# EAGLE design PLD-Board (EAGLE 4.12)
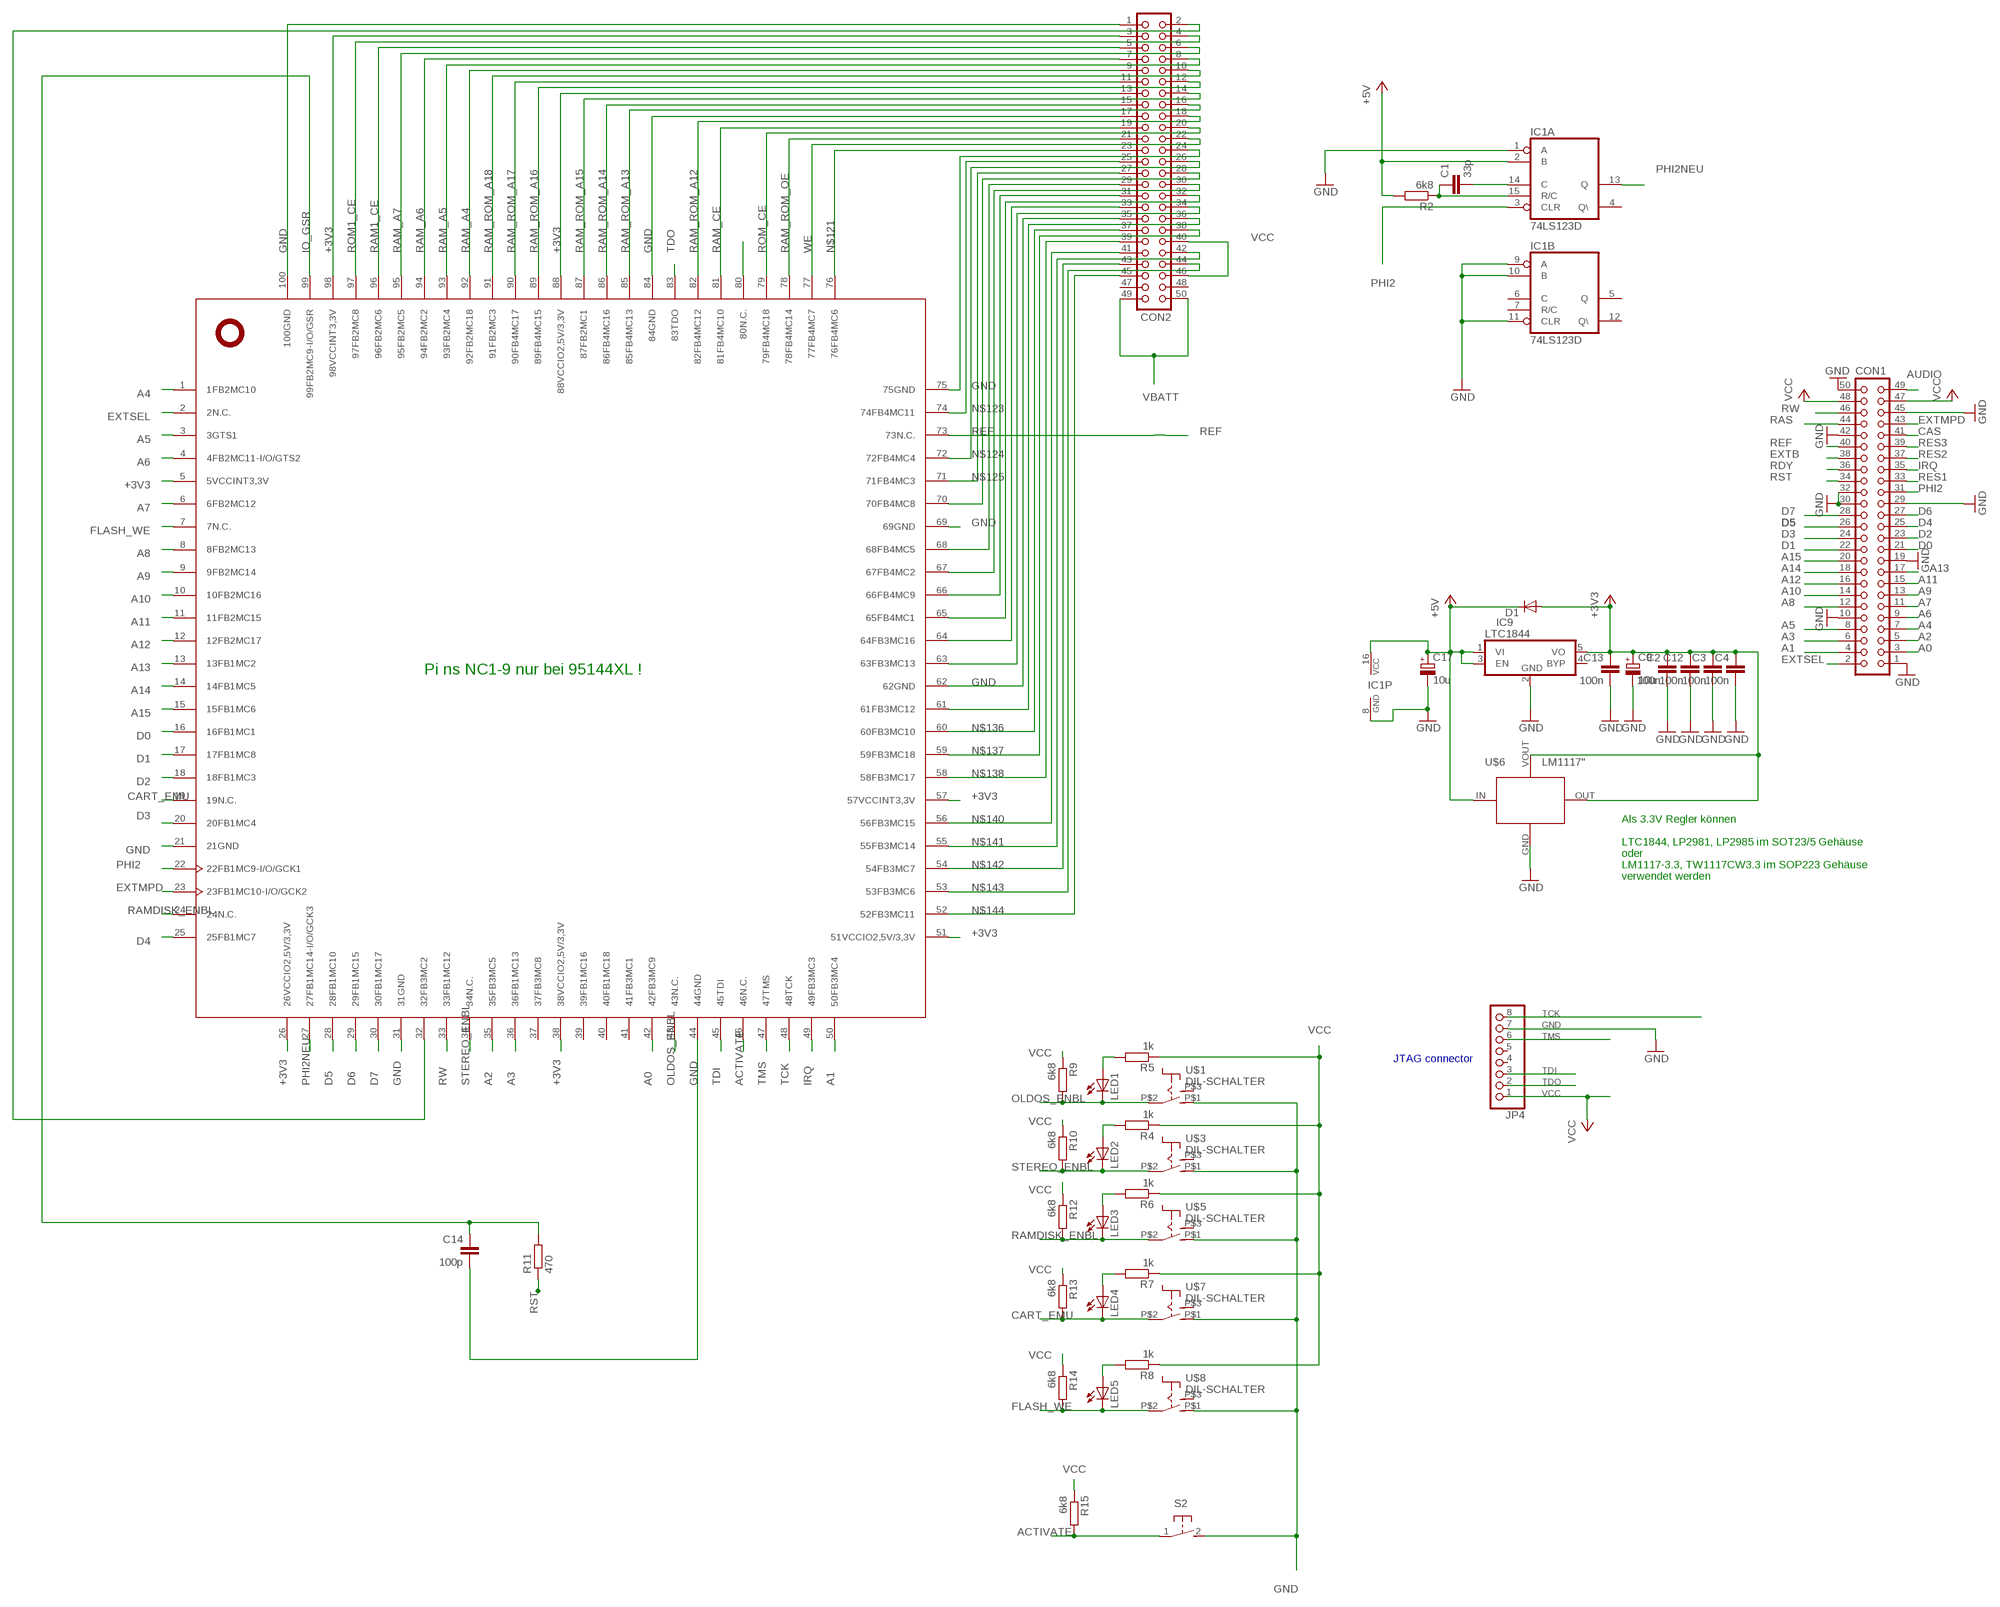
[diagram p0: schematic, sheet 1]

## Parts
C1  33p  C-EUC0805  [C0805]
C2  100n  C-EUC1206  [C1206]
C3  100n  C-EUC1206  [C1206]
C4  100n  C-EUC1206  [C1206]
C9  10u  CPOL-EUB/3528-21W  [B/3528-21W]
C12  100n  C-EUC1206  [C1206]
C13  100n  C-EUC1206  [C1206]
C14  100p  C-EUC0805  [C0805]
C17  10u  CPOL-EUB/3528-21W  [B/3528-21W]
CON1  CON50  [CON50]
CON2  CON50  [CON50]
D1  DIODE-DO214BA  [DO-214BA]
IC1  74LS123D  [SO16]
IC9  LTC1844  [SOT23/5]
JP4  PINHD-1X8  [1X08]
LED1  LEDCHIPLED_1206  [CHIPLED_1206]
LED2  LEDCHIPLED_1206  [CHIPLED_1206]
LED3  LEDCHIPLED_1206  [CHIPLED_1206]
LED4  LEDCHIPLED_1206  [CHIPLED_1206]
LED5  LEDCHIPLED_1206  [CHIPLED_1206]
R2  6k8  R-EU_M0805  [M0805]
R4  1k  R-EU_M0805  [M0805]
R5  1k  R-EU_M0805  [M0805]
R6  1k  R-EU_M0805  [M0805]
R7  1k  R-EU_M0805  [M0805]
R8  1k  R-EU_M0805  [M0805]
R9  6k8  R-EU_M0805  [M0805]
R10  6k8  R-EU_M0805  [M0805]
R11  470  R-EU_M0805  [M0805]
R12  6k8  R-EU_M0805  [M0805]
R13  6k8  R-EU_M0805  [M0805]
R14  6k8  R-EU_M0805  [M0805]
R15  6k8  R-EU_M0805  [M0805]
S2  31-XX  [B3F-31XX]
U$1  DIL-SCHALTER  [DIL-SCHALTER]
U$2  XC9572XLTQ100  [TQ100]
U$3  DIL-SCHALTER  [DIL-SCHALTER]
U$5  DIL-SCHALTER  [DIL-SCHALTER]
U$6  LM1117"  [SOT-223]
U$7  DIL-SCHALTER  [DIL-SCHALTER]
U$8  DIL-SCHALTER  [DIL-SCHALTER]

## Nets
+3V3: C2.1 C3.1 C4.1 C9.+ C12.1 C13.1 CON2.3 CON2.13 D1.A IC9.5(VO) U$2.5(5VCCINT3,3V) U$2.26(26VCCIO2,5V/3,3V) U$2.38(38VCCIO2,5V/3,3V) U$2.51(51VCCIO2,5V/3,3V) U$2.57(57VCCINT3,3V) U$2.88(88VCCIO2,5V/3,3V) U$2.98(98VCCINT3,3V) U$6.OUT U$6.VOUT(CASE)
A0: CON1.3 U$2.42(42FB3MC9)
A1: CON1.4 U$2.50(50FB3MC4)
A2: CON1.5 U$2.35(35FB3MC5)
A3: CON1.6 U$2.36(36FB1MC13)
A4: CON1.7 U$2.1(1FB2MC10)
A5: CON1.8 U$2.3(3GTS1)
A6: CON1.9 U$2.4(4FB2MC11-I/O/GTS2)
A7: CON1.11 U$2.6(6FB2MC12)
A8: CON1.12 U$2.8(8FB2MC13)
A9: CON1.13 U$2.9(9FB2MC14)
A10: CON1.14 U$2.10(10FB2MC16)
A11: CON1.15 U$2.11(11FB2MC15)
A12: CON1.16 U$2.12(12FB2MC17)
A13: CON1.17 U$2.13(13FB1MC2)
A14: CON1.18 U$2.14(14FB1MC5)
A15: CON1.20 U$2.15(15FB1MC6)
ACTIVATE: R15.2 S2.1(P) U$2.46(46N.C.)
AUDIO: CON1.49
CART_EMU: LED4.C R13.2 U$2.19(19N.C.) U$7.P$2(P)
CAS: CON1.41
D0: CON1.21 U$2.16(16FB1MC1)
D1: CON1.22 U$2.17(17FB1MC8)
D2: CON1.23 U$2.18(18FB1MC3)
D3: CON1.24 U$2.20(20FB1MC4)
D4: CON1.25 U$2.25(25FB1MC7)
D5: CON1.26 U$2.28(28FB1MC10)
D6: CON1.27 U$2.29(29FB1MC15)
D7: CON1.28 U$2.30(30FB1MC17)
DEB_LED1: CON2.28 U$2.70(70FB4MC8)
DEB_LED2: CON2.29 U$2.68(68FB4MC5)
DEB_LED3: CON2.30 U$2.67(67FB4MC2)
DEB_LED4: CON2.32 U$2.65(65FB4MC1)
DEB_LED5: CON2.31 U$2.66(66FB4MC9)
DEB_LED6: CON2.34 U$2.63(63FB3MC13)
DEB_LED7: CON2.33 U$2.64(64FB3MC16)
DEB_LED8: CON2.36 U$2.61(61FB3MC12)
EXTB: CON1.38
EXTMPD: CON1.43 U$2.23(23FB1MC10-I/O/GCK2)
EXTSEL: CON1.2 U$2.2(2N.C.)
FLASH_WE: LED5.C R14.2 U$2.7(7N.C.) U$8.P$2(P)
GND: C2.2 C3.2 C4.2 C9.- C12.2 C13.2 C14.2 C17.- CON1.1 CON1.10 CON1.19 CON1.29 CON1.30 CON1.32 CON1.42 CON1.45 CON1.50 CON2.1 CON2.17 CON2.24 CON2.35 IC1.1(A:A) IC1.8(P:GND) IC1.9(B:A) IC1.10(B:B) IC1.11(B:CLR) IC9.2(GND) JP4.7 S2.2(S) U$1.P$1(S) U$2.21(21GND) U$2.31(31GND) U$2.44(44GND) U$2.62(62GND) U$2.69(69GND) U$2.75(75GND) U$2.84(84GND) U$2.100(100GND) U$3.P$1(S) U$5.P$1(S) U$6.GND U$7.P$1(S) U$8.P$1(S)
IO_GSR: CON2.2 U$2.32(32FB3MC2)
IRQ: CON1.35 U$2.49(49FB3MC3)
N$16: C14.1 R11.2 U$2.99(99FB2MC9-I/O/GSR)
N$28: LED5.A R8.2
N$29: C1.2 IC1.14(A:C)
N$30: LED1.A R5.2
N$31: LED2.A R4.2
N$32: LED3.A R6.2
N$33: LED4.A R7.2
N$34: C1.1 IC1.15(A:R/C) R2.1
N$38: U$2.80(80N.C.)
N$121: CON2.23 U$2.76(76FB4MC6)
N$123: CON2.25 U$2.74(74FB4MC11)
N$124: CON2.26 U$2.72(72FB4MC4)
N$125: CON2.27 U$2.71(71FB4MC3)
N$136: CON2.37 U$2.60(60FB3MC10)
N$137: CON2.38 U$2.59(59FB3MC18)
N$138: CON2.39 U$2.58(58FB3MC17)
N$140: CON2.41 U$2.56(56FB3MC15)
N$141: CON2.42 U$2.55(55FB3MC14)
N$142: CON2.43 U$2.54(54FB3MC7)
N$143: CON2.44 U$2.53(53FB3MC6)
N$144: CON2.45 U$2.52(52FB3MC11)
OLDOS_ENBL: LED1.C R9.2 U$1.P$2(P) U$2.43(43N.C.)
PHI2: CON1.31 IC1.3(A:CLR) U$2.22(22FB1MC9-I/O/GCK1)
PHI2NEU: IC1.13(A:Q) U$2.27(27FB1MC14-I/O/GCK3)
RAM1_CE: CON2.5 U$2.96(96FB2MC6)
RAM_A4: CON2.9 U$2.92(92FB2MC18)
RAM_A5: CON2.8 U$2.93(93FB2MC4)
RAM_A6: CON2.7 U$2.94(94FB2MC2)
RAM_A7: CON2.6 U$2.95(95FB2MC5)
RAM_CE: CON2.19 U$2.81(81FB4MC10)
RAM_ROM_A12: CON2.18 U$2.82(82FB4MC12)
RAM_ROM_A13: CON2.16 U$2.85(85FB4MC13)
RAM_ROM_A14: CON2.15 U$2.86(86FB4MC16)
RAM_ROM_A15: CON2.14 U$2.87(87FB2MC1)
RAM_ROM_A16: CON2.12 U$2.89(89FB4MC15)
RAM_ROM_A17: CON2.11 U$2.90(90FB4MC17)
RAM_ROM_A18: CON2.10 U$2.91(91FB2MC3)
RAM_ROM_OE: CON2.21 U$2.78(78FB4MC14)
RAMDISK_ENBL: LED3.C R12.2 U$2.24(24N.C.) U$5.P$2(P)
RAS: CON1.44
RDY: CON1.36
REF: CON1.40 U$2.73(73N.C.)
RES1: CON1.33
RES2: CON1.37
RES3: CON1.39
ROM1_CE: CON2.4 U$2.97(97FB2MC8)
ROM_CE: CON2.20 U$2.79(79FB4MC18)
RST: CON1.34 R11.1
RW: CON1.46 U$2.33(33FB1MC12)
STEREO_ENBL: LED2.C R10.2 U$2.34(34N.C.) U$3.P$2(P)
TCK: JP4.8 U$2.48(48TCK)
TDI: JP4.3 U$2.45(45TDI)
TDO: JP4.2 U$2.83(83TDO)
TMS: JP4.6 U$2.47(47TMS)
VBATT: CON2.49 CON2.50
VCC: C17.+ CON1.47 CON1.48 CON2.40 CON2.46 D1.C IC1.2(A:B) IC1.16(P:VCC) IC9.1(VI) IC9.3(EN) JP4.1 R2.2 R4.1 R5.1 R6.1 R7.1 R8.1 R9.1 R10.1 R12.1 R13.1 R14.1 R15.1 U$6.IN ; supply symbol labelled +5V
WE: CON2.22 U$2.77(77FB4MC7)
Unconnected: CON2.47 CON2.48 IC1.4(A:Q\) IC1.5(B:Q) IC1.6(B:C) IC1.7(B:R/C) IC1.12(B:Q\) IC9.4(BYP) JP4.4 JP4.5 U$1.P$3(S1) U$2.37(37FB3MC8) U$2.39(39FB1MC16) U$2.40(40FB1MC18) U$2.41(41FB3MC1) U$3.P$3(S1) U$5.P$3(S1) U$7.P$3(S1) U$8.P$3(S1)

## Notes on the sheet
- Pi ns NC1-9 nur bei 95144XL !
- Als 3.3V Regler können
- LTC1844, LP2981, LP2985 im SOT23/5 Gehäuse
- oder
- LM1117-3.3, TW1117CW3.3 im SOP223 Gehäuse
- verwendet werden
- JTAG connector

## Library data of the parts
C1-C4 C12-C14 = rcl:C-EU: CAPACITOR, European symbol
C9 C17 = rcl:CPOL-EU: POLARIZED CAPACITOR, European symbol
CON1 CON2 = con-harting:CON50: CONNECTOR
D1 = diode:DIODE-: DIODE
IC1 = 74xx-eu:74*123: Retriggerable monostable MULTIVIBRATOR
IC9 = Sonstiges:LTC1844
JP4 = pinhead:PINHD-1X8: PIN HEADER
LED1-LED5 = led:LED: LED
R2 R4-R15 = rcl:R-EU_: RESISTOR, European symbol
S2 = switch-omron:31-XX: OMRON SWITCH
U$1 U$3 U$5 U$7 U$8 = wf-atari:DIL-SCHALTER
U$2 = xilinx_xc9572xl-tq100:XC9572XLTQ100
U$6 = lm1117:LM1117

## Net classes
2 3.3: width 0.508 mm, drill 0.254 mm

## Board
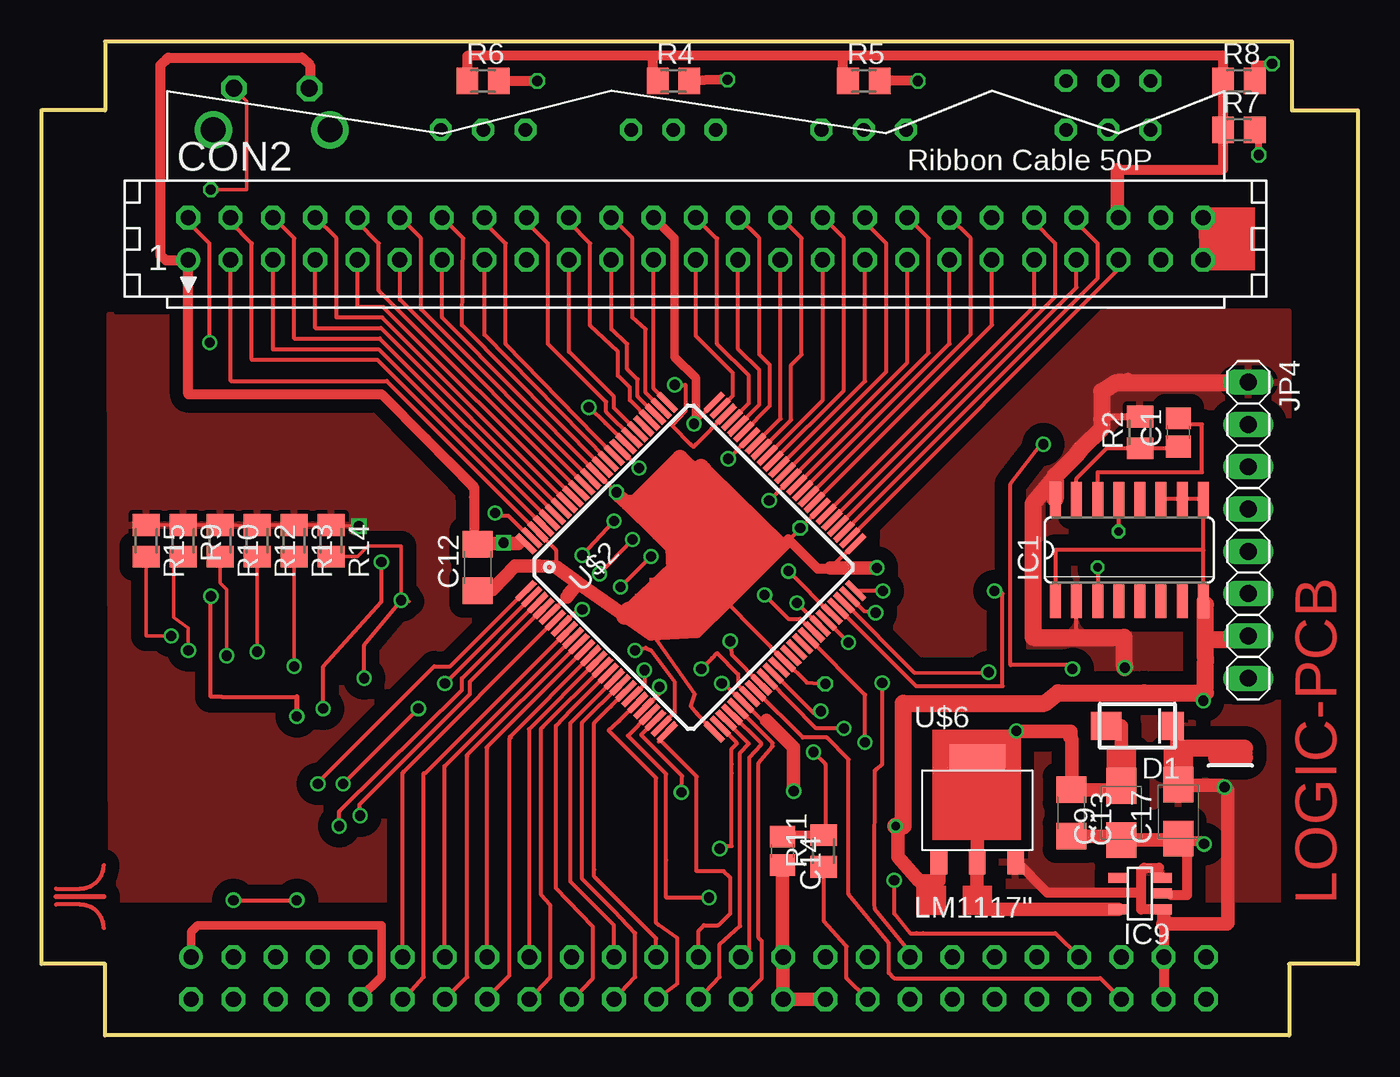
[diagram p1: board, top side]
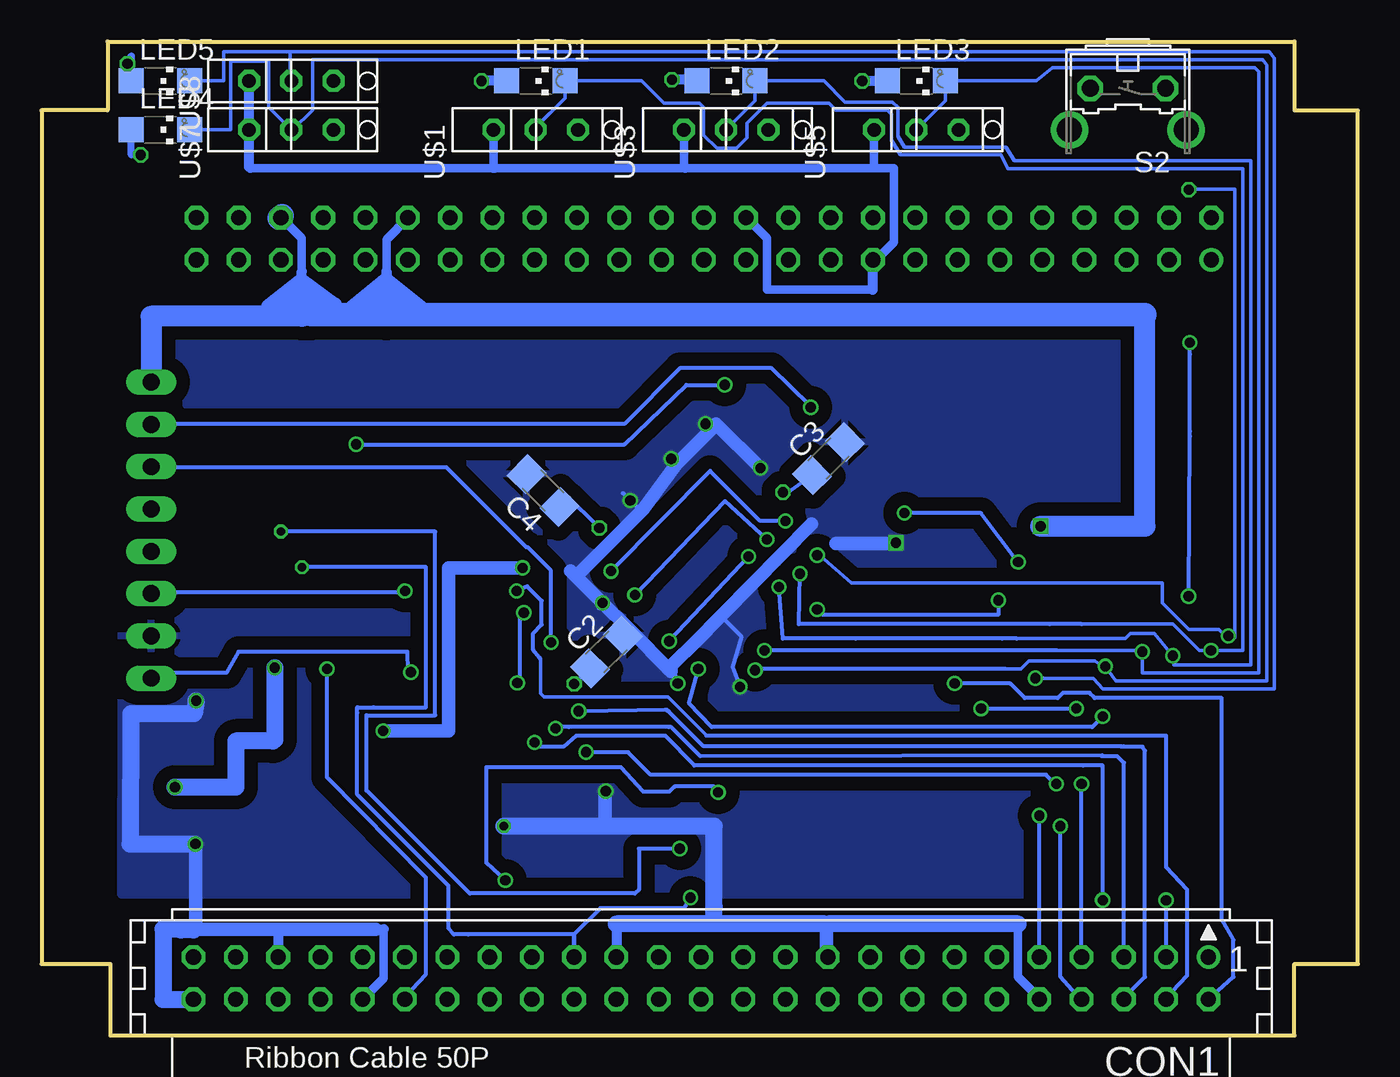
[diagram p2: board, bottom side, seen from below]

Size 79.06 x 59.69 mm. Coordinates in mm from the lower left corner, seen from the top.
Outline: 75.09,59.69 75.09,59.69
Outline: 75.09,59.69 3.81,59.69 3.81,55.56 0,55.56 0,4.29 3.81,4.29 3.81,0 74.93,0 74.93,4.29 79.06,4.29 79.06,55.56 75.09,55.56 75.09,59.69
Copper layers (1*16): Top 0.035mm / dielectric 1.5mm / Bottom 0.035mm
Design rules "ITead_rule": minimum track width 6mil, minimum drill 12mil, track to track 6mil, track to pad 6mil, pad to pad 6mil, via to via 6mil, smd to smd 0mil, copper to edge 10mil, drill to drill 10mil, minimum pad ring 10mil, minimum via ring 6mil, stop-mask expansion 2mil, vias tented up to drill 100mil, thermal gap 10mil

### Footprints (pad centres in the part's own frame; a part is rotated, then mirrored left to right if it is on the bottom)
C0805 = smd 1.3 x 1.5: 1 -0.85,0; 2 0.85,0
C1206 = smd 1.6 x 1.8: 1 -1.4,0; 2 1.4,0
B/3528-21W = smd 2.15 x 1.8: + 1.625,0; - -1.625,0
CON50 = drill 0.914 round: 1 -30.48,-1.27 | drill 0.914 octagon: 2 -30.48,1.27; 3 -27.94,-1.27; 4 -27.94,1.27; 5 -25.4,-1.27; 6 -25.4,1.27; 7 -22.86,-1.27; 8 -22.86,1.27; 9 -20.32,-1.27; 10 -20.32,1.27; 11 -17.78,-1.27; 12 -17.78,1.27; 13 -15.24,-1.27; 14 -15.24,1.27; 15 -12.7,-1.27; 16 -12.7,1.27; 17 -10.16,-1.27; 18 -10.16,1.27; 19 -7.62,-1.27; 20 -7.62,1.27; 21 -5.08,-1.27; 22 -5.08,1.27; 23 -2.54,-1.27; 24 -2.54,1.27; 25 0,-1.27; 26 0,1.27; 27 2.54,-1.27; 28 2.54,1.27; 29 5.08,-1.27; 30 5.08,1.27; 31 7.62,-1.27; 32 7.62,1.27; 33 10.16,-1.27; 34 10.16,1.27; 35 12.7,-1.27; 36 12.7,1.27; 37 15.24,-1.27; 38 15.24,1.27; 39 17.78,-1.27; 40 17.78,1.27; 41 20.32,-1.27; 42 20.32,1.27; 43 22.86,-1.27; 44 22.86,1.27; 45 25.4,-1.27; 46 25.4,1.27; 47 27.94,-1.27; 48 27.94,1.27; 49 30.48,-1.27; 50 30.48,1.27
DO-214BA = smd 1.85 x 1.68: A 1.87,0 | smd 1.32 x 1.68: C -2.12,0
SO16 = smd 0.66 x 2.032: 1 -4.445,-3.073; 2 -3.175,-3.073; 3 -1.905,-3.073; 4 -0.635,-3.073; 5 0.635,-3.073; 6 1.905,-3.073; 7 3.175,-3.073; 8 4.445,-3.073; 9 4.445,3.073; 10 3.175,3.073; 11 1.905,3.073; 12 0.635,3.073; 13 -0.635,3.073; 14 -1.905,3.073; 15 -3.175,3.073; 16 -4.445,3.073
SOT23/5 = smd 0.6 x 1.2: 1 -0.95,-1.306; 2 0,-1.306; 3 0.95,-1.306; 4 0.95,1.306; 5 -0.95,1.306
1X08 = drill 1.016 long: 1 -8.89,0; 2 -6.35,0; 3 -3.81,0; 4 -1.27,0; 5 1.27,0; 6 3.81,0; 7 6.35,0; 8 8.89,0
CHIPLED_1206 = smd 1.5 x 1.5: A 0,-1.75; C 0,1.75
M0805 = smd 1.3 x 1.6: 1 -0.95,0; 2 0.95,0
B3F-31XX = drill 1.016 octagon: 1 -2.261,-1.245; 2 2.261,-1.245 | drill 1.499 pad 2.159 round: 3 -3.505,1.245; 4 3.505,1.245
DIL-SCHALTER = drill 0.813 octagon: P$1 0,2.54; P$2 0,0; P$3 0,-2.54
TQ100 = smd 1.5 x 0.35: 1 -4.19,3.46; 2 -4.19,2.96; 3 -4.19,2.46; 4 -4.19,1.96; 5 -4.19,1.46; 6 -4.19,0.96; 7 -4.19,0.46; 8 -4.19,-0.04; 9 -4.19,-0.54; 10 -4.19,-1.04; 11 -4.19,-1.54; 12 -4.19,-2.04; 13 -4.19,-2.54; 14 -4.19,-3.04; 15 -4.19,-3.54; 16 -4.19,-4.04; 17 -4.19,-4.54; 18 -4.19,-5.04; 19 -4.19,-5.54; 20 -4.19,-6.04; 21 -4.19,-6.54; 22 -4.19,-7.04; 23 -4.19,-7.54; 24 -4.19,-8.04; 25 -4.19,-8.54; 51 11.81,-8.54; 52 11.81,-8.04; 53 11.81,-7.54; 54 11.81,-7.04; 55 11.81,-6.54; 56 11.81,-6.04; 57 11.81,-5.54; 58 11.81,-5.04; 59 11.81,-4.54; 60 11.81,-4.04; 61 11.81,-3.54; 62 11.81,-3.04; 63 11.81,-2.54; 64 11.81,-2.04; 65 11.81,-1.54; 66 11.81,-1.04; 67 11.81,-0.54; 68 11.81,-0.04; 69 11.81,0.46; 70 11.81,0.96; 71 11.81,1.46; 72 11.81,1.96; 73 11.81,2.46; 74 11.81,2.96; 75 11.81,3.46 | smd 0.35 x 1.5: 26 -2.19,-10.54; 27 -1.69,-10.54; 28 -1.19,-10.54; 29 -0.69,-10.54; 30 -0.19,-10.54; 31 0.31,-10.54; 32 0.81,-10.54; 33 1.31,-10.54; 34 1.81,-10.54; 35 2.31,-10.54; 36 2.81,-10.54; 37 3.31,-10.54; 38 3.81,-10.54; 39 4.31,-10.54; 40 4.81,-10.54; 41 5.31,-10.54; 42 5.81,-10.54; 43 6.31,-10.54; 44 6.81,-10.54; 45 7.31,-10.54; 46 7.81,-10.54; 47 8.31,-10.54; 48 8.81,-10.54; 49 9.31,-10.54; 50 9.81,-10.54; 76 9.81,5.46; 77 9.31,5.46; 78 8.81,5.46; 79 8.31,5.46; 80 7.81,5.46; 81 7.31,5.46; 82 6.81,5.46; 83 6.31,5.46; 84 5.81,5.46; 85 5.31,5.46; 86 4.81,5.46; 87 4.31,5.46; 88 3.81,5.46; 89 3.31,5.46; 90 2.81,5.46; 91 2.31,5.46; 92 1.81,5.46; 93 1.31,5.46; 94 0.81,5.46; 95 0.31,5.46; 96 -0.19,5.46; 97 -0.69,5.46; 98 -1.19,5.46; 99 -1.69,5.46; 100 -2.19,5.46
SOT-223 = smd 1 x 1.5: GND -2.3,-3; IN 2.3,-3; OUT 0,-3 | smd 3.3 x 1.5: VOUT 0,3.3

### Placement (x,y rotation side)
C1  68.27,36.22 90 top
C2  45.14,23.03 45 bottom
C3  31.8,34.64 45 bottom
C4  48.94,32.72 135 bottom
C9  64.86,13.36 90 top
C12  26.2,28.1 90 top
C13  61.84,13.36 270 top
C14  44.51,11.08 270 top
C17  68.27,13.44 90 top
CON1  39.46,3.43 180 bottom
CON2  39.29,47.84 0 top
D1  65.81,18.59 180 top
IC1  65.33,29.15 0 top
IC9  65.97,8.51 90 top
JP4  72.48,30.34 270 top
LED1  49.38,57.33 270 bottom
LED2  37.95,57.33 270 bottom
LED3  26.52,57.33 270 bottom
LED4  71.92,54.39 270 bottom
LED5  71.92,57.33 270 bottom
R2  65.97,36.22 90 top
R4  37.95,57.33 0 top
R5  49.38,57.33 0 top
R6  26.52,57.33 0 top
R7  71.92,54.39 0 top
R8  71.92,57.33 0 top
R9  8.5,29.71 270 top
R10  10.72,29.71 270 top
R11  46.97,11.07 90 top
R12  12.95,29.71 270 top
R13  15.17,29.71 270 top
R14  17.39,29.71 270 top
R15  6.28,29.71 270 top
S2  13.81,55.64 180 bottom
U$1  49.38,54.39 90 bottom
U$2  34.5,27.22 45 top
U$3  37.95,54.39 90 bottom
U$5  26.52,54.39 90 bottom
U$6  56.2,13.41 0 top
U$7  64.06,54.39 90 bottom
U$8  64.06,57.33 90 bottom

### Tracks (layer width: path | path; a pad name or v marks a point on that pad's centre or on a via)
+3V3  (via drill 0.61)
  Top 0.229: 11.36,39.31 20.73,39.31 U$2.98 30.88,29.15 30.88,28.2 | 24.06,46.56 24.06,43.12 33.19,33.91 | 30.88,28.2 | 30.88,28.2 30.88,28.12
  Top 0.254: U$2.5 30.49,25.26 | U$2.5 30.52,25.29 | 31.56,26.33 | 30.52,25.29 31.56,26.33 | 30.52,25.29 U$2.5 | 31.68,26.53 30.52,25.29 | 34.46,32.64 | 34.46,32.64 33.33,33.77 U$2.88 33.26,33.84 33.19,33.91 | 40.39,18.22 U$2.26 | 41.12,26.02 U$2.38 44.69,22.46 45.96,21.19 v47.07,21.11 | U$2.51 47.35,28.04 47.39,28.08 | 44.64,29.53 44.62,29.51 | 44.64,29.53 44.48,29.45 | U$2.57 45.73,30.63 | 44.64,29.53 44.83,29.73 44.87,29.77 45.73,30.63 | 11.36,39.31 11.36,46.59 | 24.06,46.56 CON2.13 | 36.6,24.11 38.58,24.39 | 40.39,18.22 | 40.39,18.22 39.38,19.31 38.98,19.79 | 38.98,19.79 | 38.98,19.79 39.22,20.5 36.68,24.07 38.11,24.07 38.46,24.35 39.34,24.27 | 61.76,17.88 61.88,17.76 | 61.91,14.76 61.92,14.74 | 61.91,14.76 C13.1 | 61.88,14.78 61.91,14.76 | 64.86,15.06 | 64.86,15.06 C9.+ | 64.55,14.76 64.86,15.06 | v58.55,18.28 58.52,18.28 58.12,17.88 57.95,17.88 | C12.1 26.22,26.7 26.3,26.78 27.08,26.78 | v47.07,21.11 | 45.73,30.63 | v45.56,30.48 45.64,30.56 45.73,30.63 | 34.78,32.32 34.77,32.31 | 34.78,32.32 | v34.53,32.62 34.85,32.39 34.78,32.32
  Top 0.406: 11.36,46.61 11.36,46.59 CON2.3
  Top 0.61: 44.85,29.79 44.87,29.77 46.6,28.04 47.35,28.04 | 44.83,29.73 44.85,29.71 44.62,29.47 44.58,29.47
  Top 0.813: 27.08,26.78 28.42,28.2 29.89,28.2 30.88,28.12 32.23,27.17 | 32.23,27.17 31.56,26.33 | 32.23,27.17 31.68,26.53 | 32.23,27.17 36.6,24.11 39.34,24.27 41.12,26.02 44.58,29.47 | 44.48,29.45 40.09,33.76 38.23,32.01 36.64,30.58 34.85,32.25 34.78,32.32 34.46,32.64 | 47.39,28.08 v50.17,28.08 | 61.88,17.76 61.88,14.78 | 61.91,14.76 64.55,14.76 | IC9.5 56.88,7.56 56.52,7.6 56.16,8.08 56.16,10.3 56.2,9.9 U$6.OUT | C9.+ 64.86,14.86 | C9.+ | D1.A 64.86,18.59 C9.+ | 61.76,17.88 61.83,17.88 61.83,18.26 58.58,18.26 58.58,18.28 v58.55,18.28 | 57.95,17.88 56.2,17.88 56.2,16.67 | 56.2,16.67 U$6.VOUT | U$6.VOUT | 56.2,16.67 U$6.OUT | U$6.OUT
  Top 1.422: 26.12,26.69 26.13,26.7 C12.1
  Bottom 0.254: 46.13,22.06 46.12,22.07 | 46.13,22.06 C2.1 | v47.07,21.11 47.23,20.96 46.13,22.06 | C4.1 47.37,32.29 45.72,30.64 45.64,30.64 v45.56,30.48 | C3.1 34.69,32.3 v34.53,32.62
  Bottom 0.813: v58.55,18.28 54.74,18.28 54.62,18.28 54.62,28.08 v50.17,28.08
A0  (via drill 0.61)
  Top 0.229: 49.46,20.46 46.06,23.86
  Top 0.254: 46.06,23.86 U$2.42 | v49.46,17.6 49.46,20.46 | v11.52,8.12 v15.33,8.12
  Bottom 0.229: 41.6,18 46.96,18 47.71,17.32 49.22,17.32 49.54,17.64 49.58,17.6 v49.46,17.6
  Bottom 0.254: 41.6,18 39.85,16.21 16.52,16.21 15.33,16.21 v15.33,8.12 | 11.6,4.7 | 11.6,4.7 CON1.3 11.44,4.78 11.52,4.86 v11.52,8.12 | 11.6,4.7 11.44,4.55
A1  (via drill 0.61)
  Top 0.254: U$2.50 49.71,26.71 v50.53,26.69
  Bottom 0.203: 49.1,22.6 49.1,20.53 48.89,20.32 41.43,20.32 39.13,18.02 39.14,18.01 39.14,18
  Bottom 0.254: v50.53,26.69 49.89,26.97 49.02,26.1 49.02,24.67 49.54,24.15 49.54,23.16 49.14,22.68 49.1,22.6 | 39.14,18 11.52,18 11.52,10.1 10.25,8.75 10.25,3.59 11.6,2.16 CON1.4
A2  (via drill 0.61)
  Top 0.254: U$2.35 46.52,18.44 v48.19,18.44
  Bottom 0.254: 15.33,16.81 15.37,16.81 | 15.33,16.81 39.5,16.77 41.24,18.52 41.4,18.52 47.39,18.52 48.31,18.52 v48.19,18.44 | CON1.5 14.06,16.37 14.45,16.77 15.41,16.77 | 15.41,16.77 | 15.41,16.77 15.33,16.81
A3  (via drill 0.61)
  Top 0.254: U$2.36 46.4,19.35 47,19.51 v46.8,19.47
  Bottom 0.254: v46.8,19.47 41.52,19.55 41.6,19.55 41.4,19.47 39.3,17.36 14.21,17.36 | 14.21,17.36 14.06,17.36 | CON1.6 14.06,2.24 12.79,3.51 12.79,17.09 12.94,17.32 14.21,17.32 14.21,17.36
A4  (via drill 0.61)
  Top 0.229: 29.09,26.72 24.53,22.17 23.58,22.17 16.56,15.14
  Top 0.254: 29.18,26.81 29.09,26.72 U$2.1 | v16.6,15.1 16.56,15.14
  Bottom 0.254: CON1.7 v16.6,15.1
A5  (via drill 0.61)
  Top 0.229: U$2.3 25.25,21.45 25.25,20.74 17.91,13.48
  Top 0.254: 29.85,26.06 U$2.3 | v17.87,12.56 | 17.91,13.48 17.87,13.4 v17.87,12.56
  Bottom 0.254: 16.68,2.16 17.87,3.51 v17.87,12.56
  Bottom 1.016: 16.68,2.16 CON1.8 16.52,2.16 16.52,2.08
A6  (via drill 0.61)
  Top 0.229: 30.12,25.64 25.72,21.25 25.72,20.5 19.1,13.87
  Top 0.254: 30.12,25.64 U$2.4 | v19.14,13.2 19.1,13.87
  Bottom 0.254: CON1.9 v19.14,13.2
A7
  Top 0.229: 21.74,15.84 U$2.6
  Top 0.254: U$2.6 | 21.74,15.84 21.76,15.82 21.68,15.74 CON1.11
A8
  Top 0.229: 23.06,15.78 31.52,24.23
  Top 0.254: 31.52,24.23 U$2.8 | CON1.12 21.76,2.16 22.95,3.51 22.95,15.74 23.06,15.78
A9
  Top 0.229: 24.2,16.15 U$2.9
  Top 0.254: U$2.9 31.95,23.91 | 24.2,16.15 24.22,16.13 CON1.13
A10
  Top 0.229: 25.53,16.81 32.24,23.52
  Top 0.254: 32.24,23.52 U$2.10 | CON1.14 25.57,3.51 25.57,16.77 25.53,16.81
A11
  Top 0.229: 26.72,17.29 32.6,23.17
  Top 0.254: 32.6,23.17 U$2.11 | 26.72,17.29 26.76,17.25 CON1.15
A12
  Top 0.229: 28.13,17.94 33,22.82
  Top 0.254: 33.03,22.84 33,22.82 U$2.12 | CON1.16 26.76,2.24 28.11,3.59 28.11,17.8 28.18,17.88 28.13,17.94
A13
  Top 0.229: 29.28,18.38 33.34,22.44
  Top 0.254: 33.34,22.44 U$2.13 | 29.28,18.38 29.3,18.36 CON1.17 | 29.28,18.38
A14
  Top 0.229: 30.09,18.52 U$2.14
  Top 0.254: 33.7,22.13 U$2.14 | CON1.18 30.57,3.51 30.57,7.8 30.01,8.43 30.01,18.44 30.09,18.52 | 30.09,18.52
A15
  Top 0.229: 34.02,21.77 31.84,19.59 30.88,18.59 30.88,8.83
  Top 0.254: 34.02,21.77 U$2.15 | CON1.20 31.92,2.16 33.11,3.43 33.11,6.53 30.88,8.83 | 30.88,8.83
ACTIVATE  (via drill 0.61)
  Top 0.203: R15.2 6.28,23.99 v7.79,23.99 | v10.16,50.8 12.3,50.8 12.3,56.12 11.55,56.87 S2.1
  Top 0.254: U$2.46 47.44,25.29 v44.85,27.88 | v32.47,28.83 v34.38,30.9
  Bottom 0.203: 32.63,28.52 32.31,28.83 30.41,27.17 11.75,27.17 11.75,26.06 11.75,25.98 10.17,24.39 8.34,24.39 7.94,23.99 v7.79,23.99 | v7.79,23.99 7.94,23.91 7.39,23.91 7.39,23.99 7.39,27.88 7.39,50.82 10,50.82 v10.16,50.8 | v7.79,23.99 8.02,23.99
  Bottom 0.254: 38.9,33.9 v44.85,27.88 | 32.63,28.52 v32.47,28.83 | 38.9,33.9 | v34.38,30.9 35.9,30.9 38.9,33.9
CART_EMU  (via drill 0.61)
  Top 0.203: v15.17,22.17 R13.2
  Top 0.229: U$2.19 36.2,21.09 v36.2,21.93
  Bottom 0.203: LED4.C 67.71,54.39 67.71,58.52 65.41,58.52 65.41,55.74 U$7.P$2 63.98,54.39 62.79,55.58 62.79,58.6 5.72,58.6 5.48,58.28 5.48,21.29 14.53,21.29 v15.17,22.17 15.25,22.01 15.09,22.01 15.8,22.48 19.77,22.48 20.25,22.01 21.2,22.01
  Bottom 0.229: v36.2,21.93 36.12,22.01 21.2,22.01
D0
  Top 0.229: 34.39,21.39 31.76,18.75 31.76,9.23 33.11,7.88
  Top 0.254: 34.39,21.39 U$2.16 | 33.11,7.88 34.38,6.61 34.38,4.86 34.46,4.78 CON1.21
D1
  Top 0.229: 34.73,21.05 32.47,18.79 32.47,9.39 34.38,7.48
  Top 0.254: 34.73,21.05 U$2.17 | 34.38,7.48 35.65,6.13 35.65,3.51 CON1.22
D2
  Top 0.229: 34.18,19.75 33.19,18.75 33.19,9.94
  Top 0.254: U$2.18 35.1,20.67 34.18,19.75 | CON1.23 36.92,5.82 35.96,6.77 | 35.96,6.77 | 35.96,6.77 33.19,9.55 33.19,9.94
D3
  Top 0.254: U$2.20 34.69,18.87 34.06,18.32 36.92,15.46 36.92,6.77 37.07,6.61 | 37.07,6.61 | 37.07,6.61 38.19,5.82 38.19,3.12 CON1.24
D4
  Top 0.254: U$2.25 37.58,18.18 37.07,17.64 37.19,17.68 39.34,15.54 39.34,9.86 40.96,9.86 41.36,9.47 41.36,7.32 40.65,6.61 39.77,6.61 39.46,6.29 39.46,4.78 39.38,4.7 CON1.25 39.46,4.86 39.34,4.98
D5
  Top 0.229: 41.96,16.97 42.47,17.52 | 42.39,17.6 41.11,18.88
  Top 0.254: 41.96,16.97 41.96,6.57 40.73,5.46 40.73,3.51 CON1.26 | 41.11,18.88 U$2.28 | 42.47,17.52 42.39,17.6
D6
  Top 0.254: U$2.29 43.23,17.52 43.23,17.48 42.51,16.69 42.51,5.22 CON1.27
D7
  Top 0.254: U$2.30 41.83,19.63 43.9,17.56 43.9,17.36 43.07,16.37 43.07,5.86 43.27,5.66 43.27,3.43 CON1.28
DEB_LED1
  Top 0.229: U$2.70 43.74,37.82 43.74,40.26 43.11,40.9 43.11,47.88
  Top 0.254: CON2.28 41.84,49.13 41.84,49.15 43.11,47.88
DEB_LED2
  Top 0.229: U$2.68 44.38,37.04 44.38,46.59
  Top 0.254: 44.38,46.61 44.38,46.59 CON2.29
DEB_LED3
  Top 0.229: U$2.67 45.01,36.97 45.01,40.26 45.65,40.9 45.65,47.88
  Top 0.254: CON2.30 44.38,49.13 44.38,49.15 45.65,47.88
DEB_LED4
  Top 0.229: U$2.65 48.19,38.73 48.19,47.88
  Top 0.254: 46.87,49.15 46.6,49.15 | 46.87,49.15 CON2.32 | 48.19,47.88 46.92,49.15 46.87,49.15
DEB_LED5
  Top 0.229: U$2.66 46.92,38.17 46.92,46.59
  Top 0.254: 46.92,46.61 46.92,46.59 CON2.31
DEB_LED6
  Top 0.229: U$2.63 50.73,39.86 50.73,47.57
  Top 0.254: 49.46,49.13 49.46,49.15 | 49.46,49.13 CON2.34 | 50.73,47.57 49.46,48.84 49.46,49.13
DEB_LED7
  Top 0.229: U$2.64 49.46,39.29 49.46,46.59
  Top 0.254: 49.46,46.61 49.46,46.59 CON2.33
DEB_LED8
  Top 0.229: U$2.61 53.27,40.98 53.27,47.88
  Top 0.254: CON2.36 52,49.13 52,49.15 53.27,47.88
EXTMPD  (via drill 0.61)
  Top 0.229: 38.46,15.58 36,18.04
  Top 0.254: U$2.23 36.87,18.9 36,18.04 | v38.42,14.59 38.46,15.58 | CON1.43 60.89,6.13 52.95,6.13 52.55,6.13 52.16,6.13 51.2,7.32 v51.2,9.31
  Bottom 0.254: v38.42,14.59 38.38,14.59 38.34,14.63 38.66,14.94 41.04,14.94 41.36,14.63 42.91,14.63 44.26,16.09 52.35,16.09 52.35,15.14 52.35,10.38 v51.2,9.31
EXTSEL  (via drill 0.61)
  Top 0.229: U$2.2 24.23,21.13 v24.22,21.13
  Bottom 0.229: v24.22,21.13 20.88,21.13 20.01,20.26
  Bottom 0.254: 20.01,20.26 18.02,20.26 17.71,20.58 16.12,20.58 15.8,20.26 8.18,20.26 8.18,6.93 7.47,5.74 7.47,3.51 CON1.2
FLASH_WE  (via drill 0.61)
  Top 0.203: R14.2 18.98,28.75 19.61,29.39 21.6,29.39 v21.6,26.14 22.07,26.06
  Top 0.229: U$2.7 32.21,25.58 v32.47,25.58 | v21.6,26.14 19.37,23.44 v19.37,21.45
  Bottom 0.203: 5.01,52.81 5.01,52.88 | 18.9,21.45 15.96,21.45 15.88,21.45 15.33,20.82 5.01,20.82 5.01,52.81 | v19.37,21.45 19.45,21.45 | 64.06,57.41 U$8.P$2 | 70.25,57.41 LED5.C 68.11,57.33 68.11,59.08 65.33,59.08 64.14,59.08 | 64.14,59.08 64.06,57.41 | 64.06,57.41 63.98,57.41 64.14,57.73 64.14,59.08 | 64.14,59.08 | 64.14,59.08 60.25,59.08 53.03,59.08 5.32,59.08 5.01,58.68 5.01,52.81
  Bottom 0.229: v32.47,25.58 32.15,25.26 22.07,25.26 21.6,25.26 v21.6,26.14 | v19.37,21.45 19.29,21.53
  Bottom 0.254: 18.9,21.45 v19.37,21.45
GND  (via drill 0.51, 0.61)
  Top 0.203: 25.6,33.32 25.64,33.36
  Top 0.229: 52,46.59 52,40.42 U$2.62 | 27.71,29.55 | 27.71,29.55 v27.75,29.59 | U$2.100 29.08,29.55 27.71,29.55 | U$2.62 | U$2.62 44.69,33.12
  Top 0.254: 28.62,29.55 28.64,29.53 | v27.75,29.59 28.32,29.53 | U$2.84 34.77,35.19 v35.88,34.07 | 40.4,38.04 40.41,38.04 | 40.4,38.04 U$2.75 | 40.4,38.04 v39.18,36.73 39.3,36.93 | v43.7,32.13 U$2.62 | U$2.69 42.51,35.9 v41.24,34.63 | U$2.44 v45.37,25.98 | U$2.21 36.21,19.63 37.19,20.62 37.19,21.02 v37.11,20.94 | 43.54,18.91 44.73,17.44 42.19,19.99 U$2.31 42.11,19.99 40.88,21.21 41.2,21.06 41.04,21.06 41.12,20.98 v40.85,21.13 | 64.86,11.61 | C9.- 64.86,11.61 | 64.86,11.61 64.51,11.96 | 68.27,11.73 | 68.27,11.73 | 68.86,11.73 68.78,11.81 68.31,11.81 68.27,11.77 | 68.86,11.73 68.94,11.65 68.75,10.82 | 67.83,8.43 67.2,8.44 IC9.2 68.78,8.51 | 68.86,11.73 68.78,11.65 | 44.54,10.23 C14.2 44.51,9.65 | CON2.24 36.76,49.13 | 38.03,47.88 37.98,47.88 | 52,46.56 CON2.35 52,46.59 52,46.61 | JP4.7 72.56,23.91 72.56,23.75 72.16,23.75 | IC1.10 IC1.11 | IC1.10 68.56,32.22 68.59,32.25 | IC1.10 69.75,32.22 69.78,32.25 IC1.9 69.78,29.15 | IC1.8 69.78,29.15 | IC1.1 60.89,29.15 69.78,29.15 | 68.27,11.77 | 68.27,11.77 C17.- 68.15,11.81 | 68.15,11.81 68.11,11.85 | 68.27,11.73 68.23,11.73 68.15,11.81
  Top 0.406: 8.82,46.56 CON2.1 | 25.96,29.15 25.96,29.26 C12.2 | 25.88,32.33 25.96,32.33 25.96,32.96 25.88,32.96
  Top 0.508: 37.98,47.88 CON2.24 | 38.03,47.88 38.03,40.74 39.3,39.47 39.3,36.93 | 19.14,2.24 20.41,3.51 20.41,6.61 9.37,6.61 8.98,6.21 CON1.1
  Top 0.61: 67.83,8.43 68.78,8.43 | 68.78,11.65 68.78,8.51 | 69.9,22.44 69.9,22.64 | 69.7,20.18 69.78,20.02 | v69.82,11.49 | 68.94,11.65 69.66,11.65 v69.82,11.49 | 8.82,46.56 8.82,38.52 20.25,38.52 20.41,38.52 23.1,35.82 | 23.1,35.82 25.6,33.32 25.96,32.96 25.96,29.26 | 72.52,23.79 72.16,23.75 | 72.56,23.99 | JP4.7 72.56,23.99 | 72.56,23.99 72.31,23.75 | 19.14,2.24 CON1.10 | 7.15,58.28 7.51,58.64 | 7.15,58.28 7.15,46.85 7.47,46.53 8.58,46.53 8.66,46.61 8.7,46.57 CON2.1 | 23.1,35.82 25.88,32.96 | 7.15,58.28 7.16,58.28 7.62,58.74 15.64,58.74 16.11,58.26 16.11,56.91 16.09,56.89 S2.2
  Top 0.813: C12.2 26.19,29.54 26.2,29.55 27.71,29.55 28.62,29.55 | v45.17,14.67 45.17,17.29 43.54,18.91 | 64.51,11.96 C13.2 | 68.27,11.73 C9.- | C14.2 44.51,4.57 44.54,4.55 CON1.29 CON1.30 | CON1.30 44.54,1.85 | 47.23,2.16 CON1.32 | CON1.30 47.23,2.16 | 47.23,2.16 | 69.78,20.58 67.63,20.58 | v69.78,20.1 69.7,20.18 v69.78,20.1 | 69.78,20.58 v69.78,20.1 | 69.78,20.58 69.9,20.58 | IC1.8 69.78,25.98 69.9,25.86 | U$6.GND 53.9,9.29 52.7,9.29 51.43,10.72 51.43,12.38 51.28,12.54 51.28,12.55 v51.28,12.56 | 66.21,20.58
  Top 1.016: 69.9,22.64 69.9,23.79 | 69.9,20.58 69.9,22.44 | 69.9,23.79 72.52,23.79 | 69.78,20.58 66.21,20.58 61.05,20.58 60.25,19.94 51.76,19.94 51.76,12.56 v51.28,12.56 | 69.9,23.79 69.9,25.86
  Bottom 0.203: U$7.P$1 66.6,54.47 | 66.6,54.47
  Bottom 0.254: v27.75,29.59 27.79,29.59 27.83,29.55 | v35.88,34.07 35.92,34.03 | 38.54,36.73 39.1,36.73 v39.18,36.73 | 43.4,31.83 43.35,31.77 | 42.93,31.59 43.4,31.83 | v43.7,32.13 44.14,32.56 43.4,31.83 | 40.88,34.27 40.92,34.31 v41.24,34.63 | 45.25,26.02 45.33,25.94 45.61,25.66 v45.37,25.98 | v37.11,20.94 37.55,22.13 37.03,23.95 38.41,25.33 | 41,21.77 v40.85,21.13 41.4,22.17 41.24,21.85 | 29.14,45.9 29.14,46.59 | 38.41,25.33 40.01,23.75 | 39.92,23.5 38.41,25.33 | 43.58,12.68 43.58,12.64 45.21,12.6 | 43.74,24.45 43.79,24.4 44.15,24.04 C2.2
  Bottom 0.508: 58.51,6.37 58.51,3.43 CON1.42 | 20.41,6.69 20.41,3.51 19.06,2.16 | 36.75,49.14 35.49,47.88 35.49,44.79 29.14,44.79 29.14,46.57 | 28.93,46.59 27.87,47.65 27.87,52.09 29.06,52.09 | 29.06,52.09 40.41,52.09 51.84,52.09 66.52,52.09 | 51.92,52.09 51.92,54.47 | 40.49,52.17 U$3.P$1 | 29.06,52.09 U$5.P$1
  Bottom 0.61: 45.09,12.76 44.26,12.68 43.58,12.68 38.7,12.52 39.42,12.68 | 38.66,12.56 38.82,12.57 | 38.7,6.73 33.94,6.65 31.99,6.69 | 31.99,6.69 31.95,6.57 31.88,6.61 31.99,6.49 | 69.82,11.53 | 69.82,11.53 v69.82,11.49 | 69.86,11.49 69.82,11.53 | 29.14,45.9 29.14,44.79 29.14,46.59 28.93,46.59 | 31.84,4.55 CON1.19 | 31.99,6.49 31.88,6.57 31.99,4.7 | 31.84,4.55 31.99,4.7 | 58.98,6.37 58.51,6.37 | CON1.42 | CON1.50 | 64.86,6.45 64.86,6.37 CON1.45 | 31.99,4.7 31.99,4.55 | 31.99,4.7 31.99,6.49 | 31.99,6.49 31.99,6.69 | CON1.29 44.69,4.7 44.54,4.86 44.54,6.69 | 31.84,6.69 31.84,4.55 | 19.06,2.16 CON1.10 | CON1.1 8.9,4.78 | 36.76,49.15 36.75,49.14 CON2.24 | 51.84,52.09 51.92,52.09 | U$1.P$1 51.92,54.47 51.84,54.55 | 40.41,52.09 40.49,52.17 | U$7.P$1 66.68,54.39 66.6,54.47 | 66.6,54.47 U$8.P$1 | 66.6,54.47 66.6,52.17 66.52,52.09 | 29.14,46.61 29.14,46.57 CON2.17
  Bottom 0.813: 27.83,29.55 31.36,29.55 | v35.88,34.07 38.54,36.73 38.54,36.69 40.92,34.31 42.93,31.59 46.88,27.64 47.27,27.88 45.33,25.94 43.79,24.4 41.24,21.85 41.28,22.13 41.44,22.01 40.98,22.46 39.92,23.5 32.83,30.7 | 69.82,6.37 64.86,6.37 58.98,6.37 | 69.82,6.37 69.9,6.37 69.94,6.33 | 44.3,12.52 44.26,12.56 45.21,12.6 45.21,14.63 v45.17,14.67 | v69.82,11.49 69.82,6.37 | 31.84,4.55 31.99,4.55 | CON1.30
  Bottom 1.016: 38.7,12.52 38.82,12.57 38.82,12.56 v51.28,12.56 | 38.66,12.56 38.66,7.72 38.7,6.73 | v69.78,20.1 69.9,19.31 73.71,19.31 73.75,11.49 69.86,11.49 | 69.94,6.33 70.69,6.33 71.76,6.37 71.76,2.16 CON1.50 | 31.99,6.69 44.54,6.69 | 20.41,6.69 31.84,6.69
  pour Bottom (isolate 0.813): 4.13,42.86 3.73,8.41 74.3,8.41 74.22,43.66 4.37,43.02
IO_GSR  (via drill 0.61)
  Top 0.254: 10.09,41.53 v10.09,41.61 10.09,47.57 8.82,48.84 | U$2.32 42.53,20.37 41.84,21.06 41.84,21.69 40.57,22.96 40.25,22.64 v39.61,22.01 | v39.61,22.01 39.77,22.01 | v39.61,22.01 | v10.17,26.37 10.17,20.34 10.8,20.34 15.33,20.34
  Top 0.305: 15.33,20.34 v15.33,19.15
  Top 0.406: 8.82,48.84 8.82,49 CON2.2
  Bottom 0.254: v39.61,22.01 40.17,19.94 38.82,18.52 15.96,18.52 v15.33,19.15 | v10.17,26.37 10.09,35.98 10.09,36.3 10.09,40.9 v10.09,41.61
IRQ  (via drill 0.61)
  Top 0.229: 50.05,15.94 50.13,15.98 | v50.09,25.38 49.42,25.46 U$2.49
  Top 0.254: 50.05,15.94 50.01,9.47 50.01,7.92 50.05,7.56 52.08,5.1 CON1.35 52.16,4.55 | 50.13,15.98 50.49,16.29 v50.49,21.17 | U$2.49
  Bottom 0.254: v50.09,25.38 50.33,25.34 50.33,23.12 50.33,22.56 50.33,21.25 50.41,21.17 v50.49,21.17
N$1
  Bottom 0.508: 57.08,49.07 58.35,47.8 58.35,45.58
  Bottom 0.61: 57.08,49.07 57.08,49.15 | 58.35,45.58 58.35,45.9 58.35,45.5 56.05,43.68 56.6,43.68 57.95,45.03 | 58.35,45.58 58.35,44.07 | 58.35,45.58 60.65,43.68 60.09,43.68 58.74,45.03
N$16  (via drill 0.61)
  Top 0.254: 45.81,12.18 44.55,12.19 C14.1 | 45.81,12.18 47.16,12.17 | 47.17,12.18 47.23,12.24 | 47.17,12.18 R11.2 | C14.1 44.66,12.21 47.17,12.18 | U$2.99 29.44,29.96 29.29,29.96 28.03,31.22 27.39,31.22 v27.23,31.37 | v20.41,28.44 20.41,26.06 16.91,22.17 v16.91,19.63 | v22.63,19.63 22.47,19.47 v18.1,15.1 | 45.81,12.17 45.81,12.18 | C14.1 46.92,11.93 47.08,12.09 47.08,16.29 v46.36,17.01
  Bottom 0.254: v27.23,31.37 22.63,31.37 v20.41,28.44 | v22.63,19.63 v16.91,19.63 | v46.36,17.01 43.82,17.01 42.47,15.66 18.74,15.66 18.02,14.94 v18.1,15.1
N$23
  Bottom 0.61: 57.39,43.76 57.39,43.99 57.87,44.47 57.87,44.07 57.95,43.99 59.14,43.99 | 59.14,43.99 59.3,43.99 | 59.14,43.99 58.74,44.39 58.74,44.47 58.66,44.55
N$28  (via drill 0.61)
  Top 0.406: R8.2 72.87,58.36 v73.9,58.36
  Bottom 0.406: LED5.A 73.67,58.84 v73.9,58.36
N$29
  Top 0.254: IC1.14 63.43,33.28 63.43,33.52 63.43,33.83 69.7,33.83 69.7,36.69 68.35,36.69 68.27,36.61 C1.2
N$30  (via drill 0.61)
  Top 0.61: v52.63,57.33 R5.2
  Bottom 0.61: LED1.A v52.63,57.33
N$31  (via drill 0.61)
  Top 0.61: R4.2 40.81,57.41 v41.2,57.41
  Bottom 0.61: LED2.A 39.77,57.33 39.85,57.25 40.01,57.41 v41.2,57.41
N$32  (via drill 0.61)
  Top 0.61: R6.2 v29.77,57.33
  Bottom 0.61: v29.77,57.33 LED3.A
N$33  (via drill 0.61)
  Top 0.406: R7.2 73.11,54.39 v73.11,52.88
  Bottom 0.406: LED4.A 73.67,52.88 v73.11,52.88
N$34
  Top 0.254: 68.27,35.27 R2.1 63.99,35.27 62.16,33.44 IC1.15
  Top 0.406: C1.1 68.19,34.97 68.27,35.27
N$35
  Top 1.016: 68.27,17.25 72.24,17.25 72.24,16.69 70.57,16.69
N$36
  Top 1: 35.48,25.56 35.24,25.56 35,25.16 38.02,28.02 37.94,29.29 37.07,30.16 | 37.07,30.16 37.62,30.16 | 37.07,30.16 35.24,31.99 35.64,31.99 38.34,34.69 39.29,33.73 39.29,33.81 39.61,34.13 39.77,33.97 39.29,33.97 36.59,31.27 36.59,31.43 36.35,31.67 36.59,31.67 38.58,33.66
N$37
  Top 0.305: 0.87,8.33 3.73,8.33
N$40
  Top 0.254: 0.87,8.81 2.3,8.81 arc90 3.73,10.24
N$41
  Top 0.254: 0.87,7.86 2.3,7.86 arc-90 3.73,6.43
N$121
  Top 0.254: 36.76,46.59 36.76,46.61 | 36.76,46.59 CON2.23 | U$2.76 36.76,38.84 36.76,46.59
N$123
  Top 0.229: U$2.74 41.52,38.43 41.52,39.79 39.3,42.01 39.3,46.59
  Top 0.254: 39.3,46.61 39.3,46.59 CON2.25
N$124
  Top 0.229: 40.57,47.88 40.57,41.53 42.47,39.63 42.47,37.97 U$2.72
  Top 0.254: CON2.26 40.52,47.88 40.57,47.88
N$125
  Top 0.229: U$2.71 43.11,37.89 43.11,39.95 41.84,41.22 41.84,46.59
  Top 0.254: 41.84,46.61 41.84,46.59 CON2.27
N$136
  Top 0.229: U$2.60 54.54,41.55 54.54,46.59
  Top 0.254: 54.54,46.61 54.54,46.59 CON2.37
N$137
  Top 0.229: U$2.59 55.81,42.11 55.81,47.88
  Top 0.254: CON2.38 54.54,49.13 54.54,49.15 55.81,47.88
N$138
  Top 0.229: U$2.58 57.08,42.67 57.08,46.59
  Top 0.254: 57.08,46.61 57.08,46.59 CON2.39
N$140
  Top 0.229: U$2.56 59.62,43.8 59.62,46.59
  Top 0.254: 59.62,46.61 59.62,46.59 CON2.41
N$141
  Top 0.229: U$2.55 60.89,44.36 60.89,47.57
  Top 0.254: 59.62,49.13 59.62,49.15 | 59.62,49.13 CON2.42 | 60.89,47.57 59.62,48.84 59.62,49.13
N$142
  Top 0.229: U$2.54 62.16,44.92 62.16,46.59
  Top 0.254: 62.16,46.61 62.16,46.59 CON2.43
N$143
  Top 0.254: U$2.53 63.43,45.49 63.43,47.57 62.16,48.84 62.16,49.13 | 62.16,49.13 62.16,49.15 | 62.16,49.13 CON2.44
N$144
  Top 0.254: 64.7,46.59 64.7,46.61 | 64.7,46.59 CON2.45 | U$2.52 64.7,46.05 64.7,46.59
OLDOS_ENBL  (via drill 0.61)
  Top 0.203: v8.82,23.12 8.82,24.47 7.94,25.1 7.94,28.75 8.5,28.68 R9.2
  Top 0.254: U$2.43 46.36,24.23 45.57,25.02 44.85,25.02 v43.42,26.45 | v33.5,27.72 v35.49,29.79
  Bottom 0.203: LED1.C 47.63,56.3 49.46,54.47 U$1.P$2 49.38,54.55 47.63,56.3 LED1.C 43.03,57.33 41.68,55.98 39.54,55.98 39.3,55.74 39.3,54.08 38.5,53.28 37.31,53.28 36.68,53.92 36.68,54.79 35.49,55.98 31.76,55.98 31.36,55.58 28.26,55.58 28.03,55.35 28.03,53.76 27.47,52.88 21.68,52.88 21.45,52.88 21.03,52.07 6.91,52.07 6.91,23.12 v8.82,23.12 | v8.82,23.12 9.45,23.12 | v8.82,23.12 9.53,23.12 11.12,24.71 16.6,24.71
  Bottom 0.229: 16.6,24.71 18.5,24.71
  Bottom 0.254: v43.42,26.45 38.03,32.09 v35.49,29.79 | v33.5,27.72 33.58,24.71 18.5,24.71
PHI2  (via drill 0.51, 0.61)
  Top 0.254: U$2.22 36.49,19.28 35.21,18 37.51,15.7 37.51,10.54 37.51,8.28 v40.09,8.28 | CON1.31 | v63.43,28.12 IC1.3
  Bottom 0.254: 47.08,6.05 CON1.31 47.08,4.62 47.08,6.05 | 47.08,6.05 45.49,7.64 40.49,7.64 v40.09,8.28 | v63.43,28.12 55.97,28.12 55.97,19.71 59.14,19.71 60.09,19.71 60.09,19.39 60.09,14.47 54.62,8.99 54.62,6.45 54.3,6.05 53.43,6.05 47.08,6.05
PHI2NEU  (via drill 0.51, 0.61)
  Top 0.229: 41.76,17.56 U$2.27 | 41.44,17.21 41.76,17.52
  Top 0.254: U$2.27 | 41.76,17.52 41.76,17.56 | 41.44,17.21 41.44,16.29 41.44,15.74 41.44,11.37 40.57,11.37 v40.73,11.21 | v64.7,30.26 IC1.13
  Bottom 0.254: v40.73,11.21 43.19,11.21 43.19,8.75 43.42,8.51 53.35,8.51 59.54,14.71 59.54,19.23 55.41,19.23 55.41,30.26 v64.7,30.26
RAM1_CE
  Top 0.229: U$2.96 20.24,41.22 13.9,41.22
  Top 0.254: 13.9,46.59 13.9,46.61 | 13.9,46.59 CON2.5 | 13.9,41.22 13.9,46.59
RAM_A4
  Top 0.229: U$2.92 20.52,43.76 18.98,43.76 18.98,46.59
  Top 0.254: 18.98,46.61 18.98,46.59 CON2.9
RAM_A5
  Top 0.229: U$2.93 20.45,43.12 17.71,43.12 17.71,47.88
  Top 0.254: CON2.8 16.44,49.13 16.44,49.15 17.71,47.88
RAM_A6
  Top 0.229: U$2.94 20.38,42.49 16.44,42.49 16.44,46.59
  Top 0.254: 16.44,46.61 16.44,46.59 CON2.7
RAM_A7
  Top 0.229: U$2.95 20.31,41.85 15.17,41.85
  Top 0.254: 15.17,41.85 15.17,47.88 13.9,49.15 13.9,49.13 CON2.6
RAM_CE
  Top 0.229: U$2.81 34.38,37.68 34.38,38.36 31.68,41.06 31.68,46.59
  Top 0.254: 31.68,46.61 31.68,46.59 CON2.19
RAM_ROM_A12
  Top 0.229: U$2.82 33.9,37.45 33.9,38.04 30.41,41.53 30.41,47.57
  Top 0.254: 29.14,49.13 29.14,49.15 | 29.14,49.13 CON2.18 | 30.41,47.57 29.14,48.84 29.14,49.13
RAM_ROM_A13
  Top 0.229: U$2.85 27.87,41.52 27.87,47.57
  Top 0.254: CON2.16 26.55,49.15 26.28,49.15 27.87,47.57
RAM_ROM_A14
  Top 0.229: U$2.86 26.6,42.09 26.6,46.59
  Top 0.254: 26.6,46.61 26.6,46.59 CON2.15
RAM_ROM_A15
  Top 0.229: U$2.87 25.25,42.65 25.33,47.88
  Top 0.254: CON2.14 24.06,49.13 24.06,49.15 25.33,47.88
RAM_ROM_A16
  Top 0.229: U$2.89 22.79,43.61 22.79,47.88
  Top 0.254: CON2.12 21.52,49.13 21.52,49.15 22.79,47.88
RAM_ROM_A17
  Top 0.229: U$2.90 21.52,44.18 21.52,46.59
  Top 0.254: 21.52,46.61 21.52,46.59 CON2.11
RAM_ROM_A18
  Top 0.229: U$2.91 20.25,44.74 20.25,47.57
  Top 0.254: 18.98,49.13 18.98,49.15 | 18.98,49.13 CON2.10 | 20.25,47.57 18.98,48.84 18.98,49.13
RAM_ROM_OE
  Top 0.229: U$2.78 35.8,38.38 35.8,39.39 35.17,40.03 35.17,41.53 34.22,42.41 34.22,46.61
  Top 0.254: 34.22,46.61 34.22,46.59 CON2.21
RAMDISK_ENBL  (via drill 0.61)
  Top 0.203: v12.94,23.04 R12.2
  Top 0.254: U$2.24 37.22,18.58 38.03,19.39 38.03,21.21 36.6,23.12 36.28,23.28 v35.65,23.12
  Bottom 0.203: 18.1,23.12 17.23,23.12 12.94,23.12 | 5.96,52.88 5.96,52.96 | U$5.P$2 | U$5.P$2 24.77,56.14 LED3.C 19.29,57.33 18.34,58.12 6.2,58.12 5.96,57.89 5.96,52.88 | 12.94,23.12 12.94,21.77 5.96,21.77 5.96,52.88 | 12.94,23.12 v12.94,23.04
  Bottom 0.229: 30.17,23.12 21.04,23.12 18.1,23.12
  Bottom 0.254: 30.17,23.12 v35.65,23.12
REF  (via drill 0.61)
  Top 0.229: U$2.73 39.3,35.5 39.14,35.34 38.98,35.5 37.87,36.61 38.66,37.49 38.66,39.07 v38.03,39.07
  Top 0.254: v61.92,22.01 61.92,22.25 58.19,22.25 58.19,33.12 60.01,35.5 v60.17,35.5
  Bottom 0.254: v38.03,39.07 40.33,39.07 44.06,35.5 v60.17,35.5 | CON1.40 57.24,2.32 55.97,3.67 55.97,9.47 61.92,15.5 v61.92,22.01
ROM1_CE
  Top 0.229: U$2.97 20.16,40.58 12.63,40.58
  Top 0.254: 12.63,40.58 12.63,47.57 11.36,48.84
  Top 0.406: 11.36,48.84 11.36,49.1 CON2.4
ROM_CE
  Top 0.229: U$2.79 35.33,38.15 35.33,38.91 34.61,39.63 34.61,41.06 32.95,42.65 32.95,47.57
  Top 0.254: 31.68,49.13 31.68,49.15 | 31.68,49.13 CON2.20 | 32.95,47.57 31.68,48.84 31.68,49.13
RST
  Top 0.254: R11.1 47,10.12 47,6.85 48.27,5.42 48.35,5.34 48.35,3.43 CON1.34
RW
  Top 0.254: 42.91,20.7 U$2.33 42.91,20.7 45.73,17.88 47.16,17.88 48.46,16.57 48.46,8.47 50.89,5.54 50.89,3.75 51.2,3.43 63.59,3.43 CON1.46
STEREO_ENBL  (via drill 0.61)
  Top 0.203: R10.2 10.72,27.17 11.12,26.77 v11.12,22.8
  Top 0.254: U$2.34 41.44,22.88 v41.36,23.67 | v34.77,26.93 v36.6,28.75
  Bottom 0.203: 20.49,23.83 19.45,23.83 18.18,23.83 16.75,23.83 13.98,23.83 13.66,24.15 12.23,24.15 v11.12,22.8 11.04,22.25 6.44,22.25 6.44,52.55 20.64,52.55 21.13,53.36 27.23,53.36 27.63,54 27.63,55.74 27.95,56.06 30.8,56.06 32.07,57.33 LED2.C 36.2,56.14 | LED2.C 36.2,56.14 | U$3.P$2 | 36.2,56.14 U$3.P$2
  Bottom 0.229: 30.17,23.83 21.36,23.83 20.49,23.83
  Bottom 0.254: v36.6,28.75 v41.36,23.67 | v34.77,26.93 34.53,23.83 30.17,23.83
TCK  (via drill 0.61)
  Top 0.229: 52.43,21.77 48.19,26.02
  Top 0.254: 48.19,26.02 U$2.48 | 52.43,21.77 v56.88,21.81
  Bottom 0.254: v56.88,21.81 56.8,21.93 | 57.04,21.89 57.08,23.04 67.24,23.04 67.95,21.77 72.08,21.77 72.48,21.37 | 72.48,21.37 | 72.48,21.37 JP4.8
  Bottom 0.406: JP4.8 | v56.88,21.81 57.04,21.89
TDI  (via drill 0.61)
  Top 0.254: U$2.45 v48.46,23.6
  Bottom 0.229: 49.93,29.31 54.74,34.11 70.61,34.11
  Bottom 0.254: v48.46,23.6 48.46,27.92 49.85,29.31 49.93,29.31 | JP4.3 72.63,34.15 72.63,34.11 70.61,34.11
TDO  (via drill 0.61)
  Top 0.229: v32.87,37.72 33.86,36.77 35.09,35.54
  Top 0.254: 35.09,35.54 U$2.83
  Bottom 0.229: 72.12,36.73 44.06,36.73 40.73,40.07
  Bottom 0.254: 72.48,36.73 JP4.2 | 72.12,36.73 72.48,36.73 | 72.48,36.73 72.48,36.77 | v32.87,37.72 32.87,37.8 35.21,40.07 40.73,40.07
TMS  (via drill 0.61)
  Top 0.254: U$2.47 52.51,20.98 | 52.51,20.98 53.55,20.98 | 52.51,20.98 57.71,20.98 57.71,26.53 57.39,26.61 | 57.39,26.61 v57.24,26.69 | 57.39,26.61 57.35,26.69
  Bottom 0.254: JP4.6 72.48,26.61 57.55,26.61 57.32,26.69 v57.24,26.69
VBATT
  Top 0.203: CON2.49 69.86,46.46 | 69.7,49.15 CON2.50
  Top 0.406: CON2.49 69.7,49.15
VCC  (via drill 0.61)
  Top 0.203: R15.1 8.42,30.66 R9.1 10.64,30.66 R10.1 12.79,30.58 R12.1 | R12.1 15.09,30.66 R13.1 17.31,30.66 R14.1 | R12.1 17.15,30.66 v19.06,30.58 18.9,30.58 | 64.62,51.14 64.7,51.14 64.69,51.13 CON2.46 | 64.66,49.11 64.66,50.23 64.7,50.27 64.7,49.07 64.62,49 64.62,49.23 64.7,49.15 64.7,48.92 | 64.62,50.03 64.62,50.74 64.7,50.82 64.7,48.92 | 64.7,48.92 64.7,48.84 64.62,48.76 | 64.62,48.76 | 64.62,48.76 64.78,48.92 64.78,49 | 64.78,49 65.17,49.39 65.17,49.47 64.62,50.03 | 64.62,50.03 64.62,49.55 64.78,49.39 64.78,49 | 64.7,48.92 64.78,49
  Top 0.254: 67.4,7.44 67.35,7.49 | 67.36,6.69 67.4,6.65 67.4,6.61 | 71.25,6.73 71.21,6.69 | C17.+ 68.31,15.1 68.39,15.02 | JP4.1 72.63,39.23 72.63,39.19 72.56,39.19 | 72.56,39.19 72.28,39.19 | 72.56,39.19 72.56,39.15 | IC9.3 67.24,10.1 67.12,10.06 | 62.16,23.83 62.16,23.91 IC1.2 | C17.+ 68.39,15.06 68.43,15.02 | IC9.1 67.35,6.65 67.4,6.61 | 67.4,6.61 67.4,6.13 67.32,6.05 67.32,6.53 67.4,6.61
  Top 0.406: 68.31,15.1 70.85,15.1 v71.05,14.9 | 65.05,39.19 64.7,39.23 | R8.1 70.97,54.55 | R2.2 63.59,37.17 63.67,36.45 | R15.1 6.28,30.5
  Top 0.61: 72.28,39.19 67.71,39.19 | 67.4,6.65 67.4,6.61 CON1.47 CON1.48 | 70.97,54.55 70.97,58.84 48.11,58.84 | R6.1 25.57,57.17 | R6.1 | 36.68,58.84 25.57,58.84 R6.1 | 48.11,58.84 36.68,58.84 | R4.1 36.68,57.33 36.68,58.84 | R5.1 48.11,57.33 48.11,58.84 | 70.97,54.55 R7.1 | 64.62,52.01 70.97,52.01 70.97,54.55 | IC9.1 66.05,7.56 66.05,8.04 66.05,8.57 | 66.05,8.57 66.05,9.9 66.21,10.06 67.12,10.06 | U$6.IN 58.56,10.41 60.4,8.57 66.05,8.57
  Top 0.813: 67.4,6.65 67.4,7.44 | 71.21,6.69 67.36,6.69 | 71.25,6.73 71.25,14.71 v71.05,14.9 70.93,15.02 68.43,15.02 68.39,15.02 | C17.+ 68.19,15.06 68.19,18.59 D1.C | 64.66,49.11 64.62,49.07 64.62,49.23 64.62,50.03 64.62,51.14 64.62,52.01 | 65.25,39.39 65.25,39.23 | 65.25,39.39
  Top 1.016: 72.56,39.19 67.71,39.19 65.05,39.19 | 64.7,39.23 65.25,39.23 65.05,39.19 | 65.05,39.19 64.5,39.19 63.67,38.68 63.67,37.01 63.67,36.45 62.47,35.26 62.16,34.87 60.89,33.6 60.89,33.52 60.81,33.44 | 65.05,22.29 v65.05,22.09 65.05,22.21 65.01,22.25 65.01,23.91 62.16,23.91 59.54,23.91 59.54,31.93 60.81,33.44 | 60.81,33.44 60.89,33.36 IC1.16 | 60.81,33.44
  Bottom 0.203: 64.66,49.11 64.66,49.04 | 64.78,49.07 64.74,49.11 CON2.46 | 63.67,48.12 64.54,49.15 | 57.07,49.09 58.43,47.73 58.43,43.36 58.35,43.28 | 57.04,49.11 57,49.15 | 57.04,49.11 CON2.40 | 58.35,47.8 57.04,49.11
  Bottom 0.406: 57.07,49.09 58.35,47.8 58.35,43.28
  Bottom 0.508: 63.43,45.9 63.43,47.88 63.67,48.12 | 63.67,48.12 64.66,49.11 | 63.67,48.12 64.66,49.04 | 64.54,49.15 64.78,49.07
  Bottom 0.61: 65.05,17.76 65.17,17.68 | 62.87,43.28 62.87,44.79 63.43,45.42 63.43,45.5 | 63.43,45.5 63.43,43.2 63.43,43.92 63.27,43.76 63.19,43.76 63.11,43.84 | 63.43,45.5 63.43,45.9 | 63.43,45.5 | 63.43,45.5 61.36,43.99 62.47,43.99 62.47,44.63 62.4,44.71 62.4,44.55 62.16,44.31 | 63.43,45.5 65.57,43.84 63.67,43.84 63.67,45.03 63.74,45.03 64.62,44.15 63.98,44.15 63.98,44.23 | 63.98,44.23 | 63.98,44.23 63.9,44.15 | 63.9,44.15 | 63.98,44.23 63.9,44.15
  Bottom 1.016: v71.05,14.9 67.4,14.9 67.4,17.68 65.17,17.68 | v65.05,22.09 65.05,17.76
  Bottom 1.27: 72.48,39.47 72.48,43.2 63.43,43.2 | 72.48,39.47 72.48,39.15 | 72.48,39.47 72.71,39.47 JP4.1 | 12.79,43.28 12.79,30.58 v19.06,30.58
  Bottom 1.422: 12.79,43.28 58.35,43.28 62.87,43.28 | 64.74,49.11 64.78,49.07 | CON2.46 64.74,49.11 | 64.74,49.11 64.62,49.23
  pour Top (isolate 0.813): 4.21,43.1 74.85,43.5 74.85,8.18 4.21,8.18 4.13,43.34
WE
  Top 0.229: U$2.77 36.28,38.61 36.28,42.41 35.49,43.12 35.49,47.88
  Top 0.254: CON2.22 34.22,49.13 34.22,49.15 35.49,47.88
(copper drawn outside any net)
  shapes: Top area x20

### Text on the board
Top: LOGIC-PCB
tStop: LOGIC-PCB
bStop: 100n | 100n | 100n
Silkscreen WF: 1K | 1K | 1K | 1K | CART | 512K | STEREO | OLD-OS | FLASH WE | 1K | ACTIVATE | Vbatt | Expansion-Connector | JTAG | vcc | PHI2SHORT | 6K8 | 33pF | SWITCH- | Pullups | Software & Logic: HIASSOFT | Hardware & Layout:MEGA-HZ | 74HCT123 | 6K8 | 6K8 | 6K8 | 6K8 | 6K8 | 6K8 | 100nF | XC95144XL | POWER- | SUPPLY | +5V | RESET- | RC | 10µF | ABBUC FREEZER 2011 | 100nF | 10µF | PCB Ver. 5.1 | TS1117CW3.3 | 100pF | 470R | +3.3V | PBI-Connector | GND | LP2985 | 1 | 49 | 2 | 50
SilkscreenWFbot: K A | K A | K A | K A | CART | BL | BL | GE | GN | K A | RT | ACTIVATE | 512K | STEREO | OLD-OS | FLASH | JTAG | VCC | 100n | 100n | 100n | have you played ATARI today???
